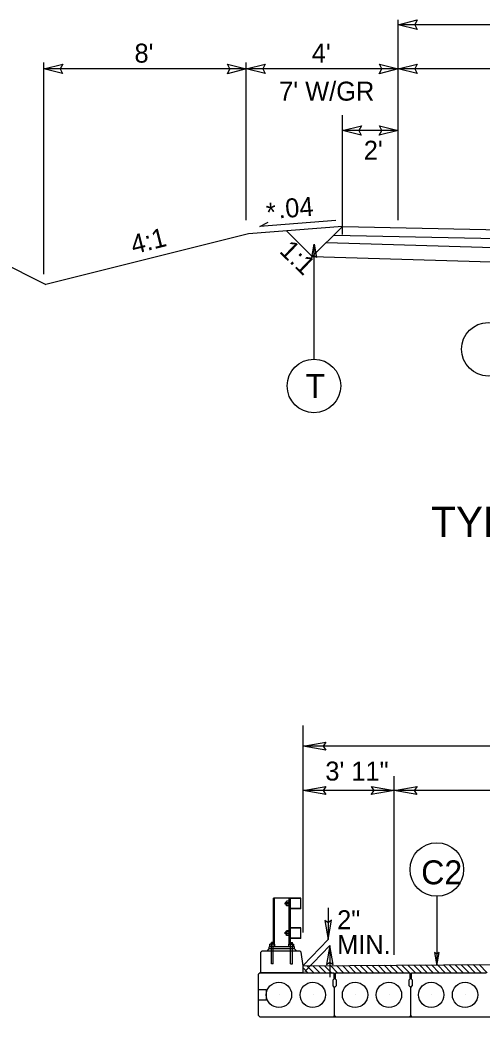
# Model space of a CAD drawing. Extents: x 575722 to 576066, y -53107 to -52774.
# Drawn here: x 575878.83 to 575897.08, y -52878.83 to -52839.41 of the extents above; entities that cross this region are included whole.
import ezdxf

# ---------------------------------------------------------------- set-up
doc = ezdxf.new("R2010")
doc.units = 0
for name, color, linetype in [('Default', 7, 'Continuous'), ('Old_Level_11', 7, 'Continuous'), ('Prop Dimension', 7, 'Continuous'), ('Prop Dimension Text', 7, 'Continuous'), ('Typical ID Circle CELL', 7, 'Continuous'), ('Typical Pavement Slope CELL', 7, 'Continuous'), ('Typical Slope Point Local CELL', 7, 'Continuous'), ('Typical Terminator CELL', 7, 'Continuous'), ('Typical Text ID Circle CELL', 7, 'Continuous')]:
    doc.layers.add(name, color=color, linetype=linetype)

# ---------------------------------------------------------------- blocks, each defined once
blk = doc.blocks.new('TERMINATOR')
at = {"layer": 'Typical Terminator CELL'}
blk.add_lwpolyline([(-0.469, 0.081), (0, 0), (-0.471, -0.083), (-0.411, 0)], close=True, dxfattribs=at)

msp = doc.modelspace()

# ---------------------------------------------------------------- linework, layer by layer
at = {"layer": 'Default'}
for p, q in [((575888.841, -52875.949), (575888.841, -52874.134)), ((575889.509, -52874.134), (575888.841, -52874.134)), ((575888.883, -52875.949), (575888.883, -52874.134)), ((575889.362, -52874.437), (575889.362, -52874.249)), ((575889.467, -52874.249), (575889.362, -52874.249)), ((575889.467, -52875.949), (575889.467, -52874.134)), ((575889.509, -52875.949), (575889.509, -52874.134)), ((575889.927, -52874.134), (575889.509, -52874.134)), ((575889.509, -52874.552), (575889.509, -52874.134)), ((575889.916, -52874.145), (575889.52, -52874.145)), ((575889.52, -52874.541), (575889.52, -52874.145)), ((575889.916, -52874.541), (575889.916, -52874.145)), ((575889.927, -52874.552), (575889.927, -52874.134)), ((575889.467, -52874.312), (575889.301, -52874.312)), ((575889.301, -52874.374), (575889.301, -52874.312)), ((575889.467, -52874.374), (575889.301, -52874.374)), ((575889.315, -52874.374), (575889.317, -52874.312)), ((575889.325, -52874.374), (575889.327, -52874.312)), ((575889.335, -52874.374), (575889.338, -52874.312)), ((575889.345, -52874.374), (575889.348, -52874.312)), ((575889.355, -52874.374), (575889.358, -52874.312)), ((575889.467, -52874.437), (575889.362, -52874.437)), ((575889.927, -52874.552), (575889.509, -52874.552)), ((575889.916, -52874.541), (575889.52, -52874.541)), ((575889.467, -52875.48), (575889.301, -52875.48)), ((575889.301, -52875.543), (575889.301, -52875.48)), ((575889.315, -52875.543), (575889.317, -52875.48)), ((575889.325, -52875.543), (575889.327, -52875.48)), ((575889.335, -52875.543), (575889.338, -52875.48)), ((575889.345, -52875.543), (575889.348, -52875.48)), ((575889.355, -52875.543), (575889.358, -52875.48)), ((575889.362, -52875.606), (575889.362, -52875.417)), ((575889.467, -52875.417), (575889.362, -52875.417)), ((575889.927, -52875.303), (575889.509, -52875.303)), ((575889.509, -52875.72), (575889.509, -52875.303)), ((575889.916, -52875.313), (575889.52, -52875.313)), ((575889.52, -52875.71), (575889.52, -52875.313)), ((575889.916, -52875.71), (575889.916, -52875.313)), ((575889.927, -52875.72), (575889.927, -52875.303)), ((575889.467, -52875.543), (575889.301, -52875.543)), ((575889.467, -52875.606), (575889.362, -52875.606)), ((575889.927, -52875.72), (575889.509, -52875.72)), ((575889.916, -52875.71), (575889.52, -52875.71)), ((575888.341, -52876.263), (575888.382, -52876.221)), ((575888.341, -52877.076), (575888.341, -52876.263)), ((575889.891, -52876.221), (575888.382, -52876.221)), ((575888.591, -52876.221), (575888.675, -52876.137)), ((575889.676, -52876.054), (575888.675, -52876.054)), ((575888.675, -52876.137), (575888.675, -52876.054)), ((575889.676, -52876.137), (575888.675, -52876.137)), ((575888.899, -52875.949), (575888.701, -52875.949)), ((575888.701, -52876.054), (575888.701, -52875.949)), ((575888.763, -52876.054), (575888.763, -52875.887)), ((575888.836, -52875.887), (575888.763, -52875.887)), ((575888.836, -52875.901), (575888.763, -52875.904)), ((575888.836, -52875.911), (575888.763, -52875.914)), ((575888.836, -52875.922), (575888.763, -52875.924)), ((575888.836, -52875.932), (575888.763, -52875.935)), ((575888.836, -52875.942), (575888.763, -52875.945)), ((575888.763, -52876.722), (575888.763, -52876.054)), ((575888.836, -52876.054), (575888.836, -52875.887)), ((575888.836, -52876.722), (575888.836, -52876.054)), ((575888.899, -52876.054), (575888.899, -52875.949)), ((575889.452, -52875.949), (575889.65, -52875.949)), ((575889.452, -52876.054), (575889.452, -52875.949)), ((575889.514, -52876.054), (575889.514, -52875.887)), ((575889.514, -52875.887), (575889.588, -52875.887)), ((575889.514, -52875.901), (575889.588, -52875.904)), ((575889.514, -52875.911), (575889.588, -52875.914)), ((575889.514, -52875.922), (575889.588, -52875.924)), ((575889.514, -52875.932), (575889.588, -52875.935)), ((575889.514, -52875.942), (575889.588, -52875.945)), ((575889.514, -52876.722), (575889.514, -52876.054)), ((575889.588, -52876.054), (575889.588, -52875.887)), ((575889.588, -52876.722), (575889.588, -52876.054)), ((575889.65, -52876.054), (575889.65, -52875.949)), ((575889.676, -52876.137), (575889.676, -52876.054)), ((575889.76, -52876.221), (575889.676, -52876.137)), ((575889.933, -52876.263), (575889.891, -52876.221)), ((575890.01, -52876.805), (575889.933, -52876.263)), ((575888.836, -52876.722), (575888.763, -52876.722)), ((575889.514, -52876.722), (575889.588, -52876.722)), ((575890.01, -52877.076), (575890.01, -52876.805)), ((575890.196, -52877.076), (575890.01, -52876.89)), ((575890.432, -52877.076), (575890.16, -52876.804)), ((575890.668, -52877.076), (575890.394, -52876.802)), ((575890.904, -52877.076), (575890.629, -52876.801)), ((575891.14, -52877.076), (575890.863, -52876.799)), ((575891.377, -52877.076), (575891.098, -52876.797)), ((575891.613, -52877.076), (575891.332, -52876.796)), ((575891.849, -52877.076), (575891.566, -52876.794)), ((575892.085, -52877.076), (575891.801, -52876.792)), ((575892.321, -52877.076), (575892.035, -52876.791)), ((575892.557, -52877.076), (575892.27, -52876.789)), ((575892.793, -52877.076), (575892.504, -52876.787)), ((575893.029, -52877.076), (575892.739, -52876.786)), ((575893.266, -52877.076), (575892.973, -52876.784)), ((575893.502, -52877.076), (575893.208, -52876.782)), ((575893.738, -52877.076), (575893.442, -52876.781)), ((575893.974, -52877.076), (575893.676, -52876.779)), ((575894.21, -52877.076), (575893.911, -52876.777)), ((575894.446, -52877.076), (575894.145, -52876.776)), ((575894.682, -52877.076), (575894.38, -52876.774)), ((575894.918, -52877.076), (575894.614, -52876.772)), ((575895.154, -52877.076), (575894.849, -52876.771)), ((575895.391, -52877.076), (575895.083, -52876.769)), ((575895.627, -52877.076), (575895.318, -52876.767)), ((575895.863, -52877.076), (575895.552, -52876.766)), ((575896.099, -52877.076), (575895.786, -52876.764)), ((575896.335, -52877.076), (575896.021, -52876.762)), ((575896.571, -52877.076), (575896.255, -52876.761)), ((575896.807, -52877.076), (575896.49, -52876.759)), ((575897.043, -52877.076), (575896.724, -52876.757)), ((575897.28, -52877.076), (575896.959, -52876.755)), ((575888.313, -52877.076), (575888.25, -52877.139)), ((575888.25, -52878.768), (575888.25, -52877.139)), ((575888.313, -52877.076), (575891.226, -52877.076)), ((575890.01, -52877.076), (575888.341, -52877.076)), ((575891.226, -52877.327), (575891.194, -52877.358)), ((575891.194, -52877.598), (575891.194, -52877.358)), ((575891.226, -52877.076), (575891.226, -52877.327)), ((575891.257, -52877.076), (575891.257, -52877.076)), ((575891.287, -52877.327), (575891.287, -52877.076)), ((575891.287, -52877.076), (575894.231, -52877.076)), ((575891.287, -52877.327), (575891.318, -52877.358)), ((575891.318, -52877.358), (575891.318, -52877.598)), ((575894.231, -52877.327), (575894.199, -52877.358)), ((575894.199, -52877.598), (575894.199, -52877.358)), ((575894.231, -52877.076), (575894.231, -52877.327)), ((575894.262, -52877.076), (575894.262, -52877.076)), ((575894.292, -52877.327), (575894.292, -52877.076)), ((575894.292, -52877.076), (575897.236, -52877.076)), ((575894.292, -52877.327), (575894.324, -52877.358)), ((575894.324, -52877.358), (575894.324, -52877.598)), ((575891.257, -52877.661), (575891.194, -52877.598)), ((575891.256, -52877.661), (575891.318, -52877.598)), ((575891.256, -52878.768), (575891.256, -52877.661)), ((575891.257, -52878.768), (575891.257, -52877.661)), ((575894.262, -52877.661), (575894.199, -52877.598)), ((575894.261, -52877.661), (575894.324, -52877.598)), ((575894.261, -52878.768), (575894.261, -52877.661)), ((575894.262, -52878.768), (575894.262, -52877.661)), ((575889.085, -52877.953), (575889.085, -52877.953)), ((575890.422, -52877.953), (575890.422, -52877.953)), ((575892.091, -52877.953), (575892.091, -52877.953)), ((575893.427, -52877.953), (575893.427, -52877.953)), ((575895.096, -52877.953), (575895.096, -52877.953)), ((575896.432, -52877.953), (575896.432, -52877.953)), ((575888.313, -52878.83), (575888.25, -52878.768)), ((575891.194, -52878.83), (575888.313, -52878.83)), ((575921.254, -52878.83), (575888.313, -52878.83)), ((575891.257, -52878.768), (575891.194, -52878.83)), ((575891.318, -52878.83), (575891.256, -52878.768)), ((575894.199, -52878.83), (575891.318, -52878.83)), ((575894.199, -52878.83), (575891.318, -52878.83)), ((575894.262, -52878.768), (575894.199, -52878.83)), ((575894.324, -52878.83), (575894.261, -52878.768)), ((575897.205, -52878.83), (575894.324, -52878.83)), ((575897.205, -52878.83), (575894.324, -52878.83))]:
    msp.add_line(p, q, dxfattribs=at)
for points in [[(575890.01, -52876.805), (575904.783, -52876.699), (575919.483, -52876.805)], [(575888.25, -52877.745), (575888.557, -52877.745), (575888.557, -52878.163), (575888.25, -52878.163)]]:
    msp.add_lwpolyline(points, dxfattribs=at)
for centre in [(575889.058, -52877.953), (575890.394, -52877.953), (575892.065, -52877.953), (575893.401, -52877.953), (575895.071, -52877.953), (575896.408, -52877.953)]:
    msp.add_circle(centre, 0.501, dxfattribs=at)
at = {"layer": 'Old_Level_11'}
for p, q in [((575890.01, -52875.493), (575890.01, -52867.304)), ((575919.483, -52868.121), (575890.01, -52868.121)), ((575893.61, -52876.376), (575893.61, -52869.304)), ((575893.61, -52869.878), (575890.01, -52869.878)), ((575909.81, -52869.878), (575893.61, -52869.878)), ((575890.012, -52876.789), (575891.002, -52875.759)), ((575890.083, -52877.024), (575891.066, -52876.001))]:
    msp.add_line(p, q, dxfattribs=at)
for points in [[(575890.91, -52868.276), (575890.01, -52868.121), (575890.915, -52867.961), (575890.8, -52868.121)], [(575890.91, -52870.033), (575890.01, -52869.878), (575890.915, -52869.718), (575890.8, -52869.878)], [(575892.71, -52869.723), (575893.61, -52869.878), (575892.705, -52870.038), (575892.82, -52869.878)], [(575894.51, -52870.033), (575893.61, -52869.878), (575894.515, -52869.718), (575894.4, -52869.878)]]:
    msp.add_lwpolyline(points, close=True, dxfattribs=at)
at = {"layer": 'Prop Dimension'}
for p, q in [((575891.002, -52874.509), (575891.002, -52875.759)), ((575891.066, -52876.001), (575891.066, -52877.251))]:
    msp.add_line(p, q, dxfattribs=at)
at = {"layer": 'Prop Dimension Text'}
for p, q in [((575893.77, -52847.332), (575893.77, -52839.415)), ((575915.77, -52839.605), (575893.77, -52839.605)), ((575879.77, -52849.463), (575879.77, -52841.102)), ((575887.77, -52846.852), (575887.77, -52841.102)), ((575887.77, -52847.332), (575887.77, -52841.102)), ((575893.77, -52846.852), (575893.77, -52841.102)), ((575893.77, -52846.852), (575893.77, -52841.122)), ((575887.77, -52841.352), (575879.77, -52841.352)), ((575893.77, -52841.352), (575887.77, -52841.352)), ((575904.77, -52841.352), (575893.77, -52841.352)), ((575891.563, -52847.89), (575891.563, -52843.178)), ((575893.77, -52843.784), (575891.563, -52843.784)), ((575889.361, -52847.754), (575890.376, -52848.769)), ((575891.568, -52847.577), (575890.376, -52848.769))]:
    msp.add_line(p, q, dxfattribs=at)
at = {"layer": 'Typical ID Circle CELL'}
for p, q in [((575890.447, -52852.824), (575890.447, -52848.284)), ((575895.295, -52874.056), (575895.295, -52876.79))]:
    msp.add_line(p, q, dxfattribs=at)
for centre in [(575897.327, -52852.432), (575890.44, -52853.882), (575895.294, -52872.999)]:
    msp.add_circle(centre, 1.058, dxfattribs=at)
at = {"layer": 'Typical Pavement Slope CELL'}
for p, q in [((575891.303, -52847.337), (575888.303, -52847.577)), ((575888.303, -52847.577), (575888.636, -52847.411)), ((575891.568, -52847.577), (575887.857, -52847.874))]:
    msp.add_line(p, q, dxfattribs=at)
for points in [[(575891.568, -52847.577), (575904.77, -52847.852)], [(575890.932, -52848.214), (575914.272, -52848.913)], [(575891.225, -52847.92), (575904.77, -52848.202)], [(575890.376, -52848.769), (575914.272, -52849.48)]]:
    msp.add_lwpolyline(points, dxfattribs=at)
at = {"layer": 'Typical Slope Point Local CELL'}
for p in [(575871.929, -52845.909), (575887.857, -52847.874)]:
    msp.add_line(p, (575879.858, -52849.874), dxfattribs=at)
at = {"layer": 'Typical Terminator CELL'}
for points in [[(575890.358, -52848.8), (575890.447, -52848.284), (575890.538, -52848.802), (575890.447, -52848.737)], [(575890.872, -52875.009), (575891.002, -52875.759), (575891.135, -52875.005), (575891.002, -52875.101)], [(575891.195, -52876.751), (575891.066, -52876.001), (575890.932, -52876.755), (575891.066, -52876.659)], [(575895.206, -52876.275), (575895.295, -52876.79), (575895.386, -52876.272), (575895.295, -52876.338)]]:
    msp.add_lwpolyline(points, close=True, dxfattribs=at)

# ---------------------------------------------------------------- block references
at = {"layer": 'Prop Dimension Text', "xscale": 1.5906680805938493, "yscale": 2.2831050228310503, "rotation": 180}
for p in [(575893.77, -52839.605), (575879.77, -52841.352), (575887.77, -52841.352), (575893.77, -52841.352), (575891.563, -52843.784)]:
    msp.add_blockref('TERMINATOR', p, dxfattribs=at)
at = {"layer": 'Prop Dimension Text', "xscale": 1.5906680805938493, "yscale": 2.2831050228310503}
for p in [(575887.77, -52841.352), (575893.77, -52841.352), (575893.77, -52843.784)]:
    msp.add_blockref('TERMINATOR', p, dxfattribs=at)

# ---------------------------------------------------------------- texts
at = {"layer": 'Old_Level_11'}
for s, p in [('3\' 11"', (575890.89, -52869.482)), ('2"', (575891.356, -52875.358)), ('MIN.', (575891.356, -52876.341))]:
    msp.add_text(s, height=0.75, rotation=360, dxfattribs=at).set_placement(p)
at = {"layer": 'Prop Dimension Text'}
for s, height, p in [("8'", 0.75, (575883.354, -52841.102)), ("4'", 0.75, (575890.354, -52841.102)), ("7' W/GR", 0.75, (575889.067, -52842.604)), ("2'", 0.75, (575892.408, -52844.94)), ('TYPICAL SECTION NO. 2', 1.2, (575895.068, -52859.851))]:
    msp.add_text(s, height=height, dxfattribs=at).set_placement(p)
for s, p in [('*', (575888.584, -52847.404)), ('.04', (575889.058, -52847.26))]:
    msp.add_text(s, height=0.75, rotation=4.5739, dxfattribs=at).set_placement(p)
at = {"layer": 'Typical Slope Point Local CELL'}
for s, rotation, p in [('4:1', 14.0362, (575883.316, -52848.68)), ('1:1', 316.0532, (575889.038, -52848.59))]:
    msp.add_text(s, height=0.75, rotation=rotation, dxfattribs=at).set_placement(p)
at = {"layer": 'Typical Text ID Circle CELL'}
for s, height, p in [('T', 0.947, (575890.106, -52854.361)), ('C2', 0.9469, (575894.677, -52873.583))]:
    msp.add_text(s, height=height, dxfattribs=at).set_placement(p)

doc.saveas('drawing.dxf')
